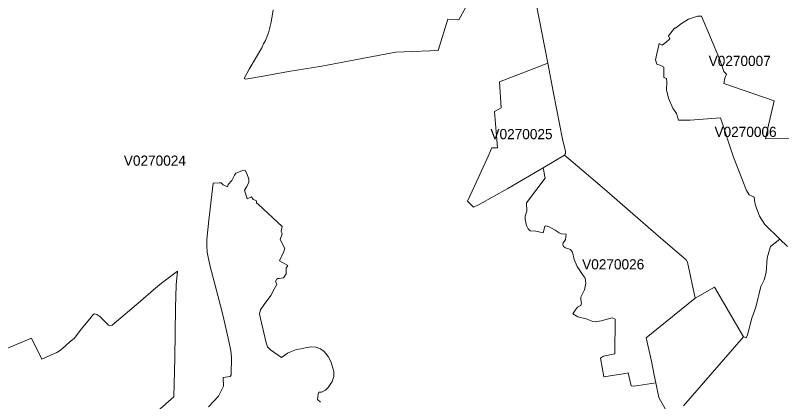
# Model space of a CAD drawing. Extents: x 369010 to 735936, y 6377141 to 6616555.
# Drawn here: x 406179 to 413706, y 6473398 to 6477197 of the extents above; entities that cross this region are included whole.
import ezdxf
from ezdxf.enums import TextEntityAlignment as Align

# ---------------------------------------------------------------- set-up
doc = ezdxf.new("R2010")
doc.units = 0
doc.header["$LTSCALE"] = 40
doc.layers.add('3', color=7, linetype='Continuous', lineweight=13)
doc.layers.add('4', color=7, linetype='Continuous')

msp = doc.modelspace()

# ---------------------------------------------------------------- linework, layer by layer
at = {"layer": '3'}
for points in [[(411390.48, 6475128.46), (411380.06, 6475120.68), (411364.5, 6475058.28), (411293, 6475075.16), (411237.06, 6475076.49), (411216.21, 6475096.02), (411198.17, 6475131.11), (411187.74, 6475188.37), (411187.74, 6475222.96), (411201.98, 6475270.96), (411199.49, 6475352.88), (411382.54, 6475595.18), (411363.51, 6475697.63), (411014.96, 6475494.72), (410734.59, 6475337.49), (410679.98, 6475311.5), (410621.55, 6475368.77), (410687.75, 6475515.74), (410810.06, 6475781.87), (410858.06, 6475893.75), (410914, 6475892.42), (410894.47, 6476133.89), (410884.04, 6476251.73), (410951.07, 6476287.32), (410933.86, 6476543.85), (411407.86, 6476726.73), (411211.57, 6477737.13)], [(411211.57, 6477737.13), (411407.86, 6476726.73), (411465.29, 6476431.8), (411554.17, 6475978.49), (411583.79, 6475858.16), (411582.47, 6475838.97), (411573.7, 6475820.26), (411784.71, 6475641.19), (411855.38, 6475584.09), (411989.77, 6475468.73), (412218, 6475267.65), (412495.39, 6475025.35), (412767.97, 6474791.33), (412780.88, 6474769.64), (412857.18, 6474416.13), (413045.36, 6474523.37), (413331.02, 6474035.3), (413358.82, 6474026.04), (413371.73, 6474055.33), (413412.61, 6474217.69), (413452.5, 6474327.75), (413502.32, 6474529.66), (413534.26, 6474596.03), (413555.11, 6474669.02), (413562.89, 6474813.01), (413596.16, 6474924.39), (413689.17, 6474995.23), (413539.88, 6475139.21), (413488.74, 6475223.13), (413454.82, 6475309.68), (413443.06, 6475354.04), (413437.27, 6475408.66), (413386.46, 6475430.17), (413361.14, 6475475.02), (413233.87, 6475802.55), (413104.44, 6476187.19), (412805.87, 6476166.66), (412693.33, 6476164.51), (412671.65, 6476232.7), (412636.89, 6476283.68), (412593.37, 6476383.14), (412574.5, 6476462.58), (412576.82, 6476543.85), (412574.83, 6476573.97), (412547.36, 6476585.89), (412547.19, 6476687.5), (412518.89, 6476703.89), (412481.49, 6476717.63), (412465.76, 6476758.34), (412501.35, 6476920.2), (412531.47, 6476903.82), (412571.52, 6476932.12), (412607.44, 6476965.88), (412593.7, 6476996.17), (412651.96, 6477069.49), (412663.21, 6477068.83), (412720.64, 6477114.67), (412790.65, 6477159.85), (412878.53, 6477188.65), (412918.58, 6477187.33), (413094.35, 6476767.28), (413139.2, 6476645.47), (413163.36, 6476617.17), (413146.32, 6476579.93), (413139.2, 6476525.48), (413630.91, 6476356.66), (413565.54, 6476074.81), (413547, 6475982.62), (413994.36, 6475985.27)], [(408710.31, 6477249.72), (408691.94, 6477128.24), (408664.63, 6477025.63), (408636.66, 6476949.83), (408616.8, 6476914.91), (408600.42, 6476877.17), (408474.97, 6476667.31), (408427.96, 6476574.96), (408438.22, 6476568.18), (408612.33, 6476597.64), (408863.24, 6476644.64), (409189.45, 6476697.6), (409586.33, 6476771.91), (409916.84, 6476835.8), (410333.58, 6476849.86), (410428.57, 6477158.2), (410534.17, 6477151.41), (410604.51, 6477276.37)], [(410604.51, 6477276.37), (410534.17, 6477151.41), (410428.57, 6477158.2), (410333.58, 6476849.86), (409916.84, 6476835.8), (409586.33, 6476771.91), (409189.45, 6476697.6), (408863.24, 6476644.64), (408612.33, 6476597.64), (408438.22, 6476568.18), (408427.96, 6476574.96), (408474.97, 6476667.31), (408600.42, 6476877.17), (408616.8, 6476914.91), (408636.66, 6476949.83), (408664.63, 6477025.63), (408691.94, 6477128.24), (408710.31, 6477249.72)], [(413994.36, 6475985.27), (413547, 6475982.62), (413565.54, 6476074.81), (413630.91, 6476356.66), (413139.2, 6476525.48), (413146.32, 6476579.93), (413163.36, 6476617.17), (413139.2, 6476645.47), (413094.35, 6476767.28), (412918.58, 6477187.33), (412878.53, 6477188.65), (412790.65, 6477159.85), (412720.64, 6477114.67), (412663.21, 6477068.83), (412651.96, 6477069.49), (412593.7, 6476996.17), (412607.44, 6476965.88), (412571.52, 6476932.12), (412531.47, 6476903.82), (412501.35, 6476920.2), (412465.76, 6476758.34), (412481.49, 6476717.63), (412518.89, 6476703.89), (412547.19, 6476687.5), (412547.36, 6476585.89), (412574.83, 6476573.97), (412576.82, 6476543.85), (412574.5, 6476462.58), (412593.37, 6476383.14), (412636.89, 6476283.68), (412671.65, 6476232.7), (412693.33, 6476164.51), (412805.87, 6476166.66), (413104.44, 6476187.19), (413233.87, 6475802.55), (413361.14, 6475475.02), (413386.46, 6475430.17), (413437.27, 6475408.66), (413443.06, 6475354.04), (413454.82, 6475309.68), (413488.74, 6475223.13), (413539.88, 6475139.21), (413689.17, 6474995.23), (413761.99, 6474923.73)], [(408076.27, 6473347.14), (408173.75, 6473452.56), (408224.39, 6473549.38), (408219.1, 6473631.31), (408220.42, 6473636.6), (408289.27, 6473644.38), (408298.37, 6473661.26), (408301.02, 6473835.54), (408294.57, 6473899.26), (408275.04, 6473994.26), (408220.59, 6474239.04), (408168.62, 6474441.78), (408089.34, 6474741.18), (408063.36, 6474868.62), (408058.06, 6474933.66), (408059.39, 6474993.57), (408080.07, 6475182.41), (408122.94, 6475545.2), (408184.01, 6475550.49), (408199.73, 6475549.17), (408219.1, 6475530.96), (408263.29, 6475508.79), (408270.73, 6475534.93), (408305.82, 6475572.67), (408330.48, 6475624.64), (408346.04, 6475644.17), (408418.86, 6475675.45), (408437.07, 6475670.15), (408453.95, 6475640.36), (408470.83, 6475585.74), (408472.15, 6475555.79), (408451.3, 6475512.92), (408429.29, 6475476.51), (408455.27, 6475393.26), (408498.14, 6475410.64), (408513.69, 6475385.98), (408533.22, 6475380.85), (408548.78, 6475374.23), (408548.78, 6475353.54), (408565.66, 6475335.34), (408799.52, 6475120.84), (408790.42, 6475075.33), (408798.2, 6475049.35), (408778.67, 6474992.08), (408826.83, 6474903.7), (408815.41, 6474873.25), (408772.38, 6474783.55), (408855.62, 6474736.71), (408837.42, 6474709.4), (408840.07, 6474683.42), (408840.07, 6474654.78), (408811.44, 6474615.73), (408790.58, 6474613.24), (408775.02, 6474607.95), (408758.14, 6474610.6), (408747.72, 6474604.14), (408733.48, 6474580.64), (408746.39, 6474549.52), (408720.41, 6474504.01), (408689.29, 6474441.45), (408621.77, 6474352.41), (408586.68, 6474300.44), (408576.25, 6474260.06), (408640.97, 6473975.72), (408655.2, 6473937.99), (408685.16, 6473909.35), (408792.4, 6473831.57), (408852.15, 6473875.76), (408875.65, 6473886.18), (408939.2, 6473912.17), (408983.39, 6473918.62), (409041.98, 6473930.37), (409088.65, 6473935.67), (409130.36, 6473933.02), (409177.03, 6473916.14), (409210.96, 6473890.16), (409252.5, 6473843.32)], [(408451.3, 6475512.92), (408472.15, 6475555.79), (408470.83, 6475585.74), (408453.95, 6475640.36), (408437.07, 6475670.15), (408418.86, 6475675.45), (408346.04, 6475644.17), (408330.48, 6475624.64), (408305.82, 6475572.67)], [(408305.82, 6475572.67), (408270.73, 6475534.93), (408263.29, 6475508.79), (408219.1, 6475530.96), (408199.73, 6475549.17), (408184.01, 6475550.49), (408122.94, 6475545.2), (408080.07, 6475182.41), (408059.39, 6474993.57), (408058.06, 6474933.66), (408063.36, 6474868.62), (408089.34, 6474741.18), (408168.62, 6474441.78), (408220.59, 6474239.04), (408275.04, 6473994.26), (408294.57, 6473899.26), (408301.02, 6473835.54), (408298.37, 6473661.26), (408289.27, 6473644.38), (408220.42, 6473636.6), (408219.1, 6473631.31), (408224.39, 6473549.38), (408173.75, 6473452.56), (408076.27, 6473347.14)], [(409177.03, 6473391.82), (409145.75, 6473420.46), (409152.21, 6473472.42), (409158.83, 6473491.95), (409187.29, 6473491.95), (409225.03, 6473512.81), (409251.01, 6473536.64), (409291.4, 6473597.88), (409308.28, 6473647.2), (409306.95, 6473694.03), (409278.32, 6473794.16), (409252.5, 6473843.32), (409210.96, 6473890.16), (409177.03, 6473916.14), (409130.36, 6473933.02), (409088.65, 6473935.67), (409041.98, 6473930.37), (408983.39, 6473918.62), (408939.2, 6473912.17), (408875.65, 6473886.18), (408852.15, 6473875.76), (408792.4, 6473831.57), (408685.16, 6473909.35), (408655.2, 6473937.99), (408640.97, 6473975.72), (408576.25, 6474260.06), (408586.68, 6474300.44), (408621.77, 6474352.41), (408689.29, 6474441.45), (408720.41, 6474504.01), (408746.39, 6474549.52), (408733.48, 6474580.64), (408747.72, 6474604.14), (408758.14, 6474610.6), (408775.02, 6474607.95), (408790.58, 6474613.24), (408811.44, 6474615.73), (408840.07, 6474654.78), (408840.07, 6474683.42), (408837.42, 6474709.4), (408855.62, 6474736.71), (408772.38, 6474783.55), (408815.41, 6474873.25), (408826.83, 6474903.7), (408778.67, 6474992.08), (408798.2, 6475049.35), (408790.42, 6475075.33), (408799.52, 6475120.84), (408565.66, 6475335.34), (408548.78, 6475353.54), (408548.78, 6475374.23), (408533.22, 6475380.85), (408513.69, 6475385.98), (408498.14, 6475410.64), (408455.27, 6475393.26), (408429.29, 6475476.51), (408451.3, 6475512.92)], [(412622.99, 6473216.72), (412500.85, 6473438.5), (412469.9, 6473583.48), (412258.55, 6473550.87), (412228.6, 6473554.85), (412198.64, 6473681.12), (412167.86, 6473674.5), (411958.66, 6473643.22), (411926.22, 6473826.11), (411957.5, 6473846.79), (412067.89, 6473867.65), (412069.55, 6474210.24), (412040.91, 6474221.99), (411931.68, 6474193.36), (411878.39, 6474184.26), (411851.25, 6474185.58), (411784.88, 6474212.89), (411702.96, 6474233.74), (411653.64, 6474261.05), (411680.94, 6474302.59), (411699.15, 6474328.58), (411732.91, 6474344.3), (411740.69, 6474365.15), (411732.91, 6474402.72), (411734.24, 6474427.22), (411768, 6474497.39), (411782.23, 6474562.43), (411774.45, 6474611.92), (411757.9, 6474638.73), (411696.83, 6474725.95), (411666.88, 6474797.45), (411652.64, 6474868.95), (411630.63, 6474893.61), (411582.47, 6474910.49), (411561.62, 6474922.24), (411555.16, 6474943.09), (411559.13, 6474959.97), (411573.37, 6474976.86), (411584.12, 6474991.92), (411589.25, 6475045.21), (411543.74, 6475047.86), (411520.4, 6475059.61), (411482.67, 6475082.94), (411416.47, 6475122), (411390.48, 6475128.46)], [(413761.99, 6474923.73), (413689.17, 6474995.23), (413596.16, 6474924.39), (413562.89, 6474813.01), (413555.11, 6474669.02), (413534.26, 6474596.03), (413502.32, 6474529.66), (413452.5, 6474327.75), (413412.61, 6474217.69), (413371.73, 6474055.33), (413358.82, 6474026.04), (413331.02, 6474035.3), (412742.32, 6473356.9)], [(407771.08, 6474682.26), (407613.85, 6474562.6), (407536.39, 6474497.72), (407406.47, 6474384.68), (407130.91, 6474150.49), (407114.03, 6474146.69), (407094.66, 6474150.49), (407007.44, 6474236.39), (406980.3, 6474255.92), (406955.47, 6474262.37), (406938.59, 6474251.95), (406924.69, 6474230.1), (406829.86, 6474114.41), (406755.71, 6474019.41), (406717.31, 6473989.96), (406670.48, 6473948.25), (406622.31, 6473904.06), (406586.07, 6473882.05), (406518.38, 6473853.41), (406439.1, 6473817), (406337.98, 6474021.24), (405733.06, 6473769.01)], [(405733.06, 6473769.01), (406337.98, 6474021.24), (406439.1, 6473817), (406518.38, 6473853.41), (406586.07, 6473882.05), (406622.31, 6473904.06), (406670.48, 6473948.25), (406717.31, 6473989.96), (406755.71, 6474019.41), (406829.86, 6474114.41), (406924.69, 6474230.1), (406938.59, 6474251.95), (406955.47, 6474262.37), (406980.3, 6474255.92), (407007.44, 6474236.39), (407094.66, 6474150.49), (407114.03, 6474146.69), (407130.91, 6474150.49), (407406.47, 6474384.68), (407536.39, 6474497.72), (407613.85, 6474562.6), (407771.08, 6474682.26), (407758.17, 6474547.21)], [(407061.73, 6472382.08), (407069.51, 6472380.76), (407191.32, 6472450.93), (407196.61, 6472454.74), (407191.32, 6472478.24), (407119.65, 6472652.85), (406939.09, 6472678.83), (406959.78, 6472703.66), (406996.19, 6472778.96), (407071.66, 6472895.97), (407306.51, 6473069.75), (407736.32, 6473444.12), (407745.26, 6473827.26), (407751.71, 6474319.14), (407758.17, 6474547.21), (407771.08, 6474682.26)], [(407758.17, 6474547.21), (407751.71, 6474319.14), (407745.26, 6473827.26), (407736.32, 6473444.12), (407306.51, 6473069.75)], [(412742.32, 6473356.9), (413331.02, 6474035.3), (413045.36, 6474523.37), (412857.18, 6474416.13), (412375.89, 6474025.04), (412426.7, 6473797.14), (412453.68, 6473658.95), (412469.9, 6473583.48), (412500.85, 6473438.5), (412622.99, 6473216.72)], [(409252.5, 6473843.32), (409278.32, 6473794.16), (409306.95, 6473694.03), (409308.28, 6473647.2), (409291.4, 6473597.88), (409251.01, 6473536.64), (409225.03, 6473512.81), (409187.29, 6473491.95), (409158.83, 6473491.95), (409152.21, 6473472.42), (409145.75, 6473420.46), (409177.03, 6473391.82)]]:
    msp.add_lwpolyline(points, dxfattribs=at)
for points in [[(411407.86, 6476726.73), (410933.86, 6476543.85), (410951.07, 6476287.32), (410884.04, 6476251.73), (410894.47, 6476133.89), (410914, 6475892.42), (410858.06, 6475893.75), (410810.06, 6475781.87), (410687.75, 6475515.74), (410621.55, 6475368.77), (410679.98, 6475311.5), (410734.59, 6475337.49), (411014.96, 6475494.72), (411363.51, 6475697.63), (411573.7, 6475820.26), (411582.47, 6475838.97), (411583.79, 6475858.16), (411554.17, 6475978.49), (411465.29, 6476431.8)], [(411573.7, 6475820.26), (411363.51, 6475697.63), (411382.54, 6475595.18), (411199.49, 6475352.88), (411201.98, 6475270.96), (411187.74, 6475222.96), (411187.74, 6475188.37), (411198.17, 6475131.11), (411216.21, 6475096.02), (411237.06, 6475076.49), (411293, 6475075.16), (411364.5, 6475058.28), (411380.06, 6475120.68), (411390.48, 6475128.46), (411416.47, 6475122), (411482.67, 6475082.94), (411520.4, 6475059.61), (411543.74, 6475047.86), (411589.25, 6475045.21), (411584.12, 6474991.92), (411573.37, 6474976.86), (411559.13, 6474959.97), (411555.16, 6474943.09), (411561.62, 6474922.24), (411582.47, 6474910.49), (411630.63, 6474893.61), (411652.64, 6474868.95), (411666.88, 6474797.45), (411696.83, 6474725.95), (411757.9, 6474638.73), (411774.45, 6474611.92), (411782.23, 6474562.43), (411768, 6474497.39), (411734.24, 6474427.22), (411732.91, 6474402.72), (411740.69, 6474365.15), (411732.91, 6474344.3), (411699.15, 6474328.58), (411680.94, 6474302.59), (411653.64, 6474261.05), (411702.96, 6474233.74), (411784.88, 6474212.89), (411851.25, 6474185.58), (411878.39, 6474184.26), (411931.68, 6474193.36), (412040.91, 6474221.99), (412069.55, 6474210.24), (412067.89, 6473867.65), (411957.5, 6473846.79), (411926.22, 6473826.11), (411958.66, 6473643.22), (412167.86, 6473674.5), (412198.64, 6473681.12), (412228.6, 6473554.85), (412258.55, 6473550.87), (412469.9, 6473583.48), (412453.68, 6473658.95), (412426.7, 6473797.14), (412375.89, 6474025.04), (412857.18, 6474416.13), (412780.88, 6474769.64), (412767.97, 6474791.33), (412495.39, 6475025.35), (412218, 6475267.65), (411989.77, 6475468.73), (411855.38, 6475584.09), (411784.71, 6475641.19)]]:
    msp.add_lwpolyline(points, close=True, dxfattribs=at)

# ---------------------------------------------------------------- texts
at = {"layer": '4'}
for s, p in [('V0270007', (413294.1, 6476698.39)), ('V0270025', (411150.7, 6475978.85)), ('V0270006', (413351.53, 6476000.83)), ('V0270024', (407549.38, 6475718.03)), ('V0270026', (412051.39, 6474698.51))]:
    msp.add_text(s, height=100, dxfattribs=at).set_placement(p, align=Align.CENTER)

doc.saveas('drawing.dxf')
